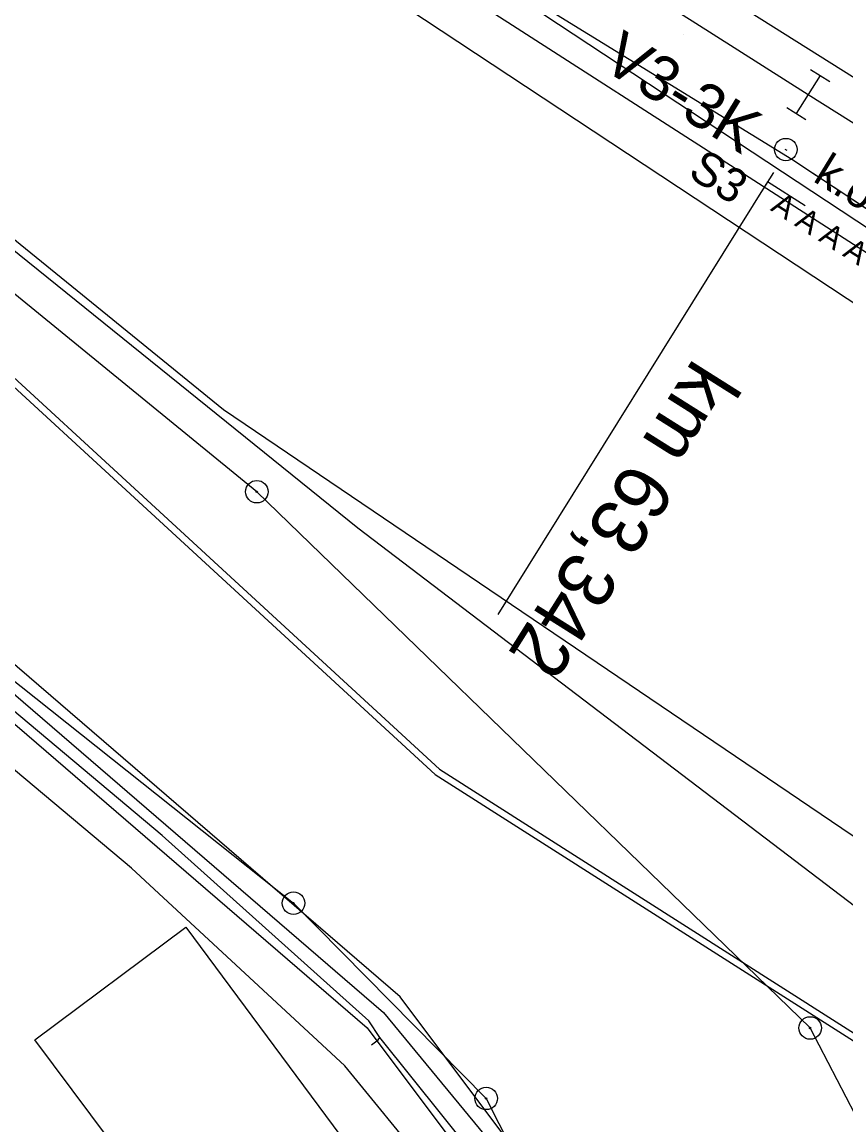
# Model space of a CAD drawing. Extents: x -620475 to -619963, y -1123010 to -1122510.
# Drawn here: x -620377.42 to -620340.78, y -1122701.38 to -1122652.35 of the extents above; entities that cross this region are included whole.
import ezdxf

# ---------------------------------------------------------------- set-up
doc = ezdxf.new("R2010")
doc.units = 0
for name, color, linetype in [('060601_EOV', 7, 'Continuous'), ('060604_ROZVODY_SEE', 7, 'Continuous'), ('CETIN', 7, 'Continuous'), ('GasNet', 7, 'Continuous'), ('HranDP', 7, 'Continuous'), ('Hranice parcel', 7, 'Continuous'), ('PS 06-14-01_trasa_sdělovací_nové', 7, 'Continuous'), ('SEE', 7, 'Continuous'), ('SSZT', 7, 'Continuous'), ('SSZT-DK', 7, 'Continuous'), ('VAS vodovod', 7, 'Continuous'), ('Vrstva 1', 7, 'Continuous'), ('Vrstva 14', 7, 'Continuous'), ('Vrstva 27', 7, 'Continuous'), ('Vrstva 3', 7, 'Continuous'), ('Vrstva 6', 7, 'Continuous'), ('Vrstva 62', 7, 'Continuous'), ('Věcná břemena k části', 7, 'Continuous'), ('Značky bodu BP', 7, 'Continuous'), ('ČD-T', 7, 'Continuous')]:
    doc.layers.add(name, color=color, linetype=linetype)

msp = doc.modelspace()

# ---------------------------------------------------------------- linework, layer by layer
at = {"layer": '060601_EOV'}
msp.add_lwpolyline([(-620235.16, -1122712.242), (-620240.174, -1122718.342), (-620243.025, -1122715.998), (-620248.321, -1122722.765), (-620259.889, -1122713.575), (-620277.713, -1122700.902), (-620282.346, -1122705.302), (-620297.82, -1122689.49), (-620304.222, -1122684.862), (-620310.815, -1122680.061), (-620322.228, -1122672.322), (-620343.182, -1122658.459), (-620368.499, -1122642.897), (-620385.559, -1122631.811)], dxfattribs=at)
at = {"layer": '060604_ROZVODY_SEE'}
msp.add_lwpolyline([(-620243.025, -1122715.998), (-620248.321, -1122722.765), (-620259.889, -1122713.575), (-620277.713, -1122700.902), (-620282.346, -1122705.302), (-620297.82, -1122689.49), (-620304.222, -1122684.862), (-620310.815, -1122680.061), (-620316.822, -1122675.988), (-620322.228, -1122672.322), (-620326.634, -1122669.408), (-620343.182, -1122658.459), (-620368.499, -1122642.897), (-620385.559, -1122631.811)], dxfattribs=at)
at = {"layer": 'CETIN'}
msp.add_lwpolyline([(-620398.075, -1122646.118), (-620362.48, -1122674.84), (-620281.95, -1122736.09)], dxfattribs=at)
at = {"layer": 'GasNet'}
msp.add_lwpolyline([(-620407.492, -1122656.883), (-620389.11, -1122672.47), (-620361.34, -1122696.38), (-620351.16, -1122708.72), (-620351, -1122709.02), (-620350.83, -1122709.39), (-620350.53, -1122710.79), (-620349.5, -1122710.44), (-620336.68, -1122702.48), (-620334.91, -1122701.4), (-620329.86, -1122698.6), (-620318.09, -1122706.99), (-620309.56, -1122715.75), (-620284.55, -1122735.89), (-620286.51, -1122738.72), (-620281.311, -1122742.821), (-620280.83, -1122743.2), (-620261.03, -1122754.43), (-620247.22, -1122761.95), (-620220.34, -1122775.27), (-620203.57, -1122783.96)], dxfattribs=at)
at = {"layer": 'HranDP'}
msp.add_lwpolyline([(-620310.57, -1122708.76), (-620306.2, -1122698.65), (-620309.9, -1122688.62), (-620334.71, -1122668.63), (-620387.366, -1122633.877)], dxfattribs=at)
at = {"layer": 'Hranice parcel'}
for points in [[(-620310.57, -1122708.76), (-620306.2, -1122698.65), (-620309.9, -1122688.62), (-620334.71, -1122668.63), (-620387.366, -1122633.877)], [(-620397.759, -1122645.758), (-620368.46, -1122669.58), (-620310.57, -1122708.76)], [(-620342.37, -1122697.07), (-620366.98, -1122673.23), (-620398.957, -1122647.127)], [(-620407.034, -1122656.36), (-620404.9, -1122658.18), (-620395.68, -1122667.41), (-620365.35, -1122691.52), (-620356.78, -1122700.2), (-620347.29, -1122718.92), (-620345.94, -1122726.44), (-620346.26, -1122738.61)], [(-620346.9, -1122728.66), (-620349.5, -1122720.4), (-620352.08, -1122712.18), (-620363.06, -1122698.75), (-620372.55, -1122689.97), (-620409.403, -1122659.069)], [(-620349.5, -1122720.4), (-620362.45, -1122730.09), (-620377.36, -1122710.19), (-620370.99, -1122705.44), (-620376.85, -1122697.59), (-620370.13, -1122692.59), (-620349.5, -1122720.4)], [(-620328.93, -1122734.05), (-620330.51, -1122726.08), (-620332.51, -1122716.01), (-620337.56, -1122706.31), (-620342.37, -1122697.07)]]:
    msp.add_lwpolyline(points, dxfattribs=at)
at = {"layer": 'PS 06-14-01_trasa_sdělovací_nové'}
msp.add_lwpolyline([(-620248.321, -1122722.765), (-620259.889, -1122713.575), (-620277.711, -1122700.887), (-620282.346, -1122705.302), (-620297.82, -1122689.49), (-620310.815, -1122680.061), (-620322.228, -1122672.322), (-620343.182, -1122658.459), (-620368.499, -1122642.897), (-620385.559, -1122631.811)], dxfattribs=at)
at = {"layer": 'SEE'}
msp.add_lwpolyline([(-620244.518, -1122694.296), (-620246.547, -1122692.66), (-620267.469, -1122718.6), (-620268.222, -1122719.534), (-620284.407, -1122704.62), (-620304.333, -1122686.26), (-620309.55, -1122681.453), (-620327.714, -1122669.483), (-620362.834, -1122646.339), (-620385.658, -1122631.923)], dxfattribs=at)
at = {"layer": 'SSZT'}
msp.add_lwpolyline([(-620386.367, -1122632.734), (-620363.271, -1122647.563), (-620313.966, -1122679.218), (-620306.51, -1122669.289), (-620273.137, -1122696.274), (-620258.422, -1122709.142), (-620248.072, -1122696.094)], dxfattribs=at)
at = {"layer": 'SSZT-DK'}
msp.add_lwpolyline([(-620400.12, -1122648.456), (-620392.309, -1122655.212), (-620359.04, -1122685.798), (-620308.772, -1122717.798), (-620291.405, -1122732.208), (-620277.196, -1122744.115), (-620257.608, -1122720.05), (-620250.251, -1122710.721), (-620233.29, -1122724.26), (-620218.699, -1122737.685), (-620210.438, -1122746.518), (-620193.319, -1122761.993), (-620178.352, -1122775.894), (-620171.184, -1122783.621), (-620164.843, -1122792.284), (-620156.695, -1122803.312), (-620146.306, -1122818.994), (-620117.638, -1122885.131), (-620110.298, -1122902.137)], dxfattribs=at)
at = {"layer": 'VAS vodovod'}
for points in [[(-620346.78, -1122722.2), (-620350.174, -1122711.617), (-620361.503, -1122697.496), (-620361.995, -1122696.756), (-620371.189, -1122688.51), (-620408.082, -1122657.558)], [(-620361.871, -1122697.817), (-620361.588, -1122697.594), (-620361.503, -1122697.496)]]:
    msp.add_lwpolyline(points, dxfattribs=at)
at = {"layer": 'Vrstva 1'}
for points in [[(-620383.649, -1122629.627), (-620378.269, -1122633.015), (-620362.958, -1122642.66), (-620347.616, -1122652.305), (-620342.456, -1122655.575), (-620322.526, -1122668.083), (-620312.925, -1122674.13), (-620301.163, -1122681.549), (-620292.126, -1122687.227), (-620282.992, -1122692.997), (-620276.394, -1122697.25), (-620266.758, -1122703.956), (-620255.894, -1122712.191)], [(-620326.634, -1122669.408), (-620343.182, -1122658.459), (-620368.499, -1122642.897), (-620385.559, -1122631.811)]]:
    msp.add_lwpolyline(points, dxfattribs=at)
at = {"layer": 'Vrstva 14'}
msp.add_lwpolyline([(-620382.462, -1122628.27), (-620376.978, -1122631.728), (-620361.983, -1122641.198), (-620346.591, -1122650.915), (-620335.3, -1122658.037), (-620326.919, -1122663.23), (-620325.66, -1122664.016), (-620320.659, -1122667.355), (-620319.405, -1122668.214), (-620318.806, -1122667.396), (-620318.045, -1122667.942), (-620316.915, -1122666.32), (-620319.344, -1122664.58), (-620319.636, -1122664.917), (-620324.475, -1122661.491), (-620327.8, -1122659.174), (-620333.678, -1122655.247), (-620340.478, -1122650.803), (-620347.325, -1122646.469), (-620355.043, -1122641.547), (-620361.891, -1122637.249), (-620368.728, -1122632.945), (-620375.571, -1122628.636), (-620379.873, -1122625.938)], dxfattribs=at)
at = {"layer": 'Vrstva 27'}
msp.add_line((-620343.494, -1122657.997), (-620343.408, -1122658.049), dxfattribs=at)
msp.add_circle((-620343.451, -1122658.023), 0.5, dxfattribs=at)
at = {"layer": 'Vrstva 3'}
for p, q in [((-620342.348, -1122654.462), (-620341.501, -1122654.994)), ((-620341.924, -1122654.728), (-620342.988, -1122656.422)), ((-620343.411, -1122656.156), (-620342.564, -1122656.688))]:
    msp.add_line(p, q, dxfattribs=at)
at = {"layer": 'Vrstva 6'}
for p, q in [((-620344.002, -1122659.038), (-620344.536, -1122659.884)), ((-620344.269, -1122659.461), (-620356.264, -1122678.683)), ((-620342.594, -1122660.517), (-620344.269, -1122659.461))]:
    msp.add_line(p, q, dxfattribs=at)
at = {"layer": 'Vrstva 62'}
for p, q in [((-620348.005, -1122652.904), (-620348.005, -1122652.904)), ((-620342.078, -1122654.983), (-620342.078, -1122654.983)), ((-620342.835, -1122656.168), (-620342.835, -1122656.168))]:
    msp.add_line(p, q, dxfattribs=at)
at = {"layer": 'Věcná břemena k části'}
msp.add_lwpolyline([(-620408.148, -1122657.633), (-620389.78, -1122673.21), (-620362.07, -1122697.07), (-620350.79, -1122712.11), (-620329.91, -1122699.79), (-620318.75, -1122707.75), (-620310.23, -1122716.49), (-620285.9, -1122736.09), (-620287.87, -1122738.92), (-620280.66, -1122744.45), (-620246.32, -1122763.41), (-620202.66, -1122784.39), (-620201.79, -1122782.59), (-620245.45, -1122761.61), (-620279.7, -1122742.7), (-620285.15, -1122738.52), (-620283.23, -1122735.73), (-620308.89, -1122715.01), (-620317.45, -1122706.23), (-620329.81, -1122697.41), (-620350.27, -1122709.47), (-620360.61, -1122695.69), (-620388.48, -1122671.69), (-620406.835, -1122656.132)], dxfattribs=at)
at = {"layer": 'Značky bodu BP'}
for centre, radius in [((-620366.98, -1122673.23), 0.5), ((-620366.98, -1122673.23), 0.0303), ((-620365.35, -1122691.52), 0.5), ((-620365.35, -1122691.52), 0.0303), ((-620342.37, -1122697.07), 0.5), ((-620342.37, -1122697.07), 0.0303), ((-620356.78, -1122700.2), 0.5), ((-620356.78, -1122700.2), 0.0303)]:
    msp.add_circle(centre, radius, dxfattribs=at)
at = {"layer": 'ČD-T'}
msp.add_lwpolyline([(-620399.923, -1122648.231), (-620392.122, -1122654.977), (-620358.852, -1122685.564), (-620308.585, -1122717.564), (-620291.218, -1122731.973), (-620279.983, -1122741.462), (-620260.482, -1122717.473), (-620252.938, -1122708.192), (-620233.103, -1122724.025), (-620218.511, -1122737.45), (-620206.638, -1122747.527), (-620193.132, -1122761.758), (-620178.165, -1122775.66), (-620170.996, -1122783.386), (-620164.655, -1122792.049), (-620156.507, -1122803.078), (-620146.119, -1122818.76), (-620117.451, -1122884.896), (-620110.11, -1122901.903)], dxfattribs=at)

# ---------------------------------------------------------------- texts
at = {"layer": 'Vrstva 27'}
for s, height, p in [('V3-3K', 2, (-620351.729, -1122654.376)), ('k.o.', 1.5, (-620342.294, -1122659.401))]:
    msp.add_text(s, height=height, rotation=328.4879, dxfattribs=at).set_placement(p)
at = {"layer": 'Vrstva 6'}
for s, height, rotation, p in [('S3', 1.5, 327.7824, (-620347.861, -1122659.197)), ('  A A A A ', 1, 327.7824, (-620344.802, -1122660.307)), ('km 63,342', 2.5, 237.7824, (-620347.531, -1122667.235))]:
    msp.add_text(s, height=height, rotation=rotation, dxfattribs=at).set_placement(p)

doc.saveas('drawing.dxf')
